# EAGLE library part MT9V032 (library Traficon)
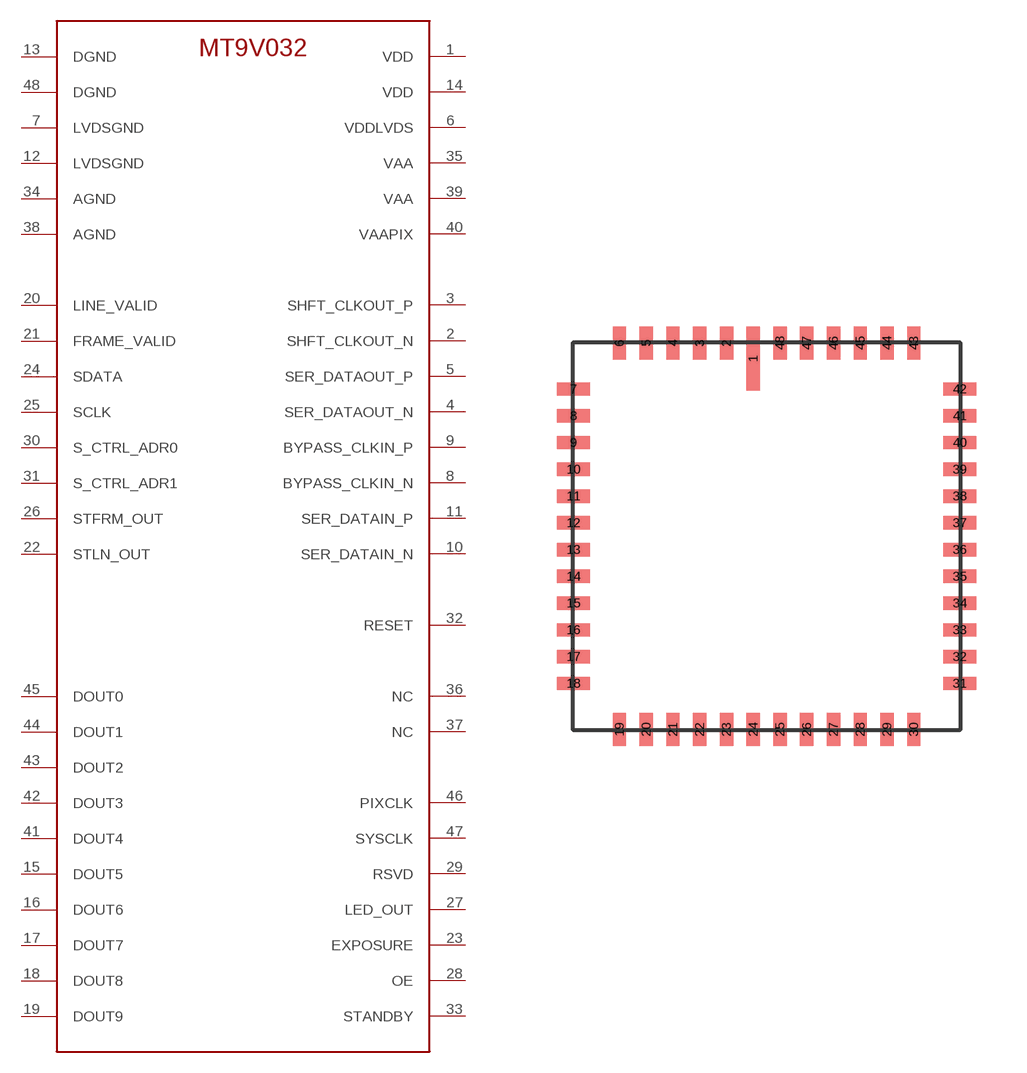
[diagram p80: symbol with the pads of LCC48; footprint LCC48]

Designator prefix U

## MT9V032  [LCC48]
1  VDD  pwr
2  SHFT_CLKOUT_N  out
3  SHFT_CLKOUT_P  out
4  SER_DATAOUT_N  out
5  SER_DATAOUT_P  out
6  VDDLVDS  pwr
7  LVDSGND  pwr
8  BYPASS_CLKIN_N  in
9  BYPASS_CLKIN_P  in
10  SER_DATAIN_N  in
11  SER_DATAIN_P  in
12  LVDSGND  pwr
13  DGND  pwr
14  VDD  pwr
15  DOUT5  out
16  DOUT6  out
17  DOUT7  out
18  DOUT8  out
19  DOUT9  out
20  LINE_VALID  out
21  FRAME_VALID  out
22  STLN_OUT
23  EXPOSURE  in
24  SDATA
25  SCLK  in
26  STFRM_OUT
27  LED_OUT  out
28  OE  in
29  RSVD  in
30  S_CTRL_ADR0  in
31  S_CTRL_ADR1  in
32  RESET  in
33  STANDBY  in
34  AGND  pwr
35  VAA  pwr
36  NC  nc
37  NC  nc
38  AGND  pwr
39  VAA  pwr
40  VAAPIX  pwr
41  DOUT4  out
42  DOUT3  out
43  DOUT2  out
44  DOUT1  out
45  DOUT0  out
46  PIXCLK  out
47  SYSCLK  in
48  DGND  pwr

## Footprint LCC48 (pad centres in mm)
smd 0.4 x 1.92: 1 -0.4,5.31
smd 0.4 x 0.99: 2 -1.2,5.775; 3 -2,5.775; 4 -2.8,5.775; 5 -3.6,5.775; 6 -4.4,5.775; 19 -4.4,-5.775; 20 -3.6,-5.775; 21 -2.8,-5.775; 22 -2,-5.775; 23 -1.2,-5.775; 24 -0.4,-5.775; 25 0.4,-5.775; 26 1.2,-5.775; 27 2,-5.775; 28 2.8,-5.775; 29 3.6,-5.775; 30 4.4,-5.775; 43 4.4,5.775; 44 3.6,5.775; 45 2.8,5.775; 46 2,5.775; 47 1.2,5.775; 48 0.4,5.775
smd 0.99 x 0.4: 7 -5.775,4.4; 8 -5.775,3.6; 9 -5.775,2.8; 10 -5.775,2; 11 -5.775,1.2; 12 -5.775,0.4; 13 -5.775,-0.4; 14 -5.775,-1.2; 15 -5.775,-2; 16 -5.775,-2.8; 17 -5.775,-3.6; 18 -5.775,-4.4; 31 5.775,-4.4; 32 5.775,-3.6; 33 5.775,-2.8; 34 5.775,-2; 35 5.775,-1.2; 36 5.775,-0.4; 37 5.775,0.4; 38 5.775,1.2; 39 5.775,2; 40 5.775,2.8; 41 5.775,3.6; 42 5.775,4.4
